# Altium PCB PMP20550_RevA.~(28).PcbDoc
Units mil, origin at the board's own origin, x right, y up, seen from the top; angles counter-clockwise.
Board outline 3847.52 x 1857.32 mil, 2 copper layers (Top Layer, Bottom Layer), stack 62 mil thick; 56 components, 23 nets, 129 pads, 22 vias.
Unrouted connection lines stored in the file: 87.
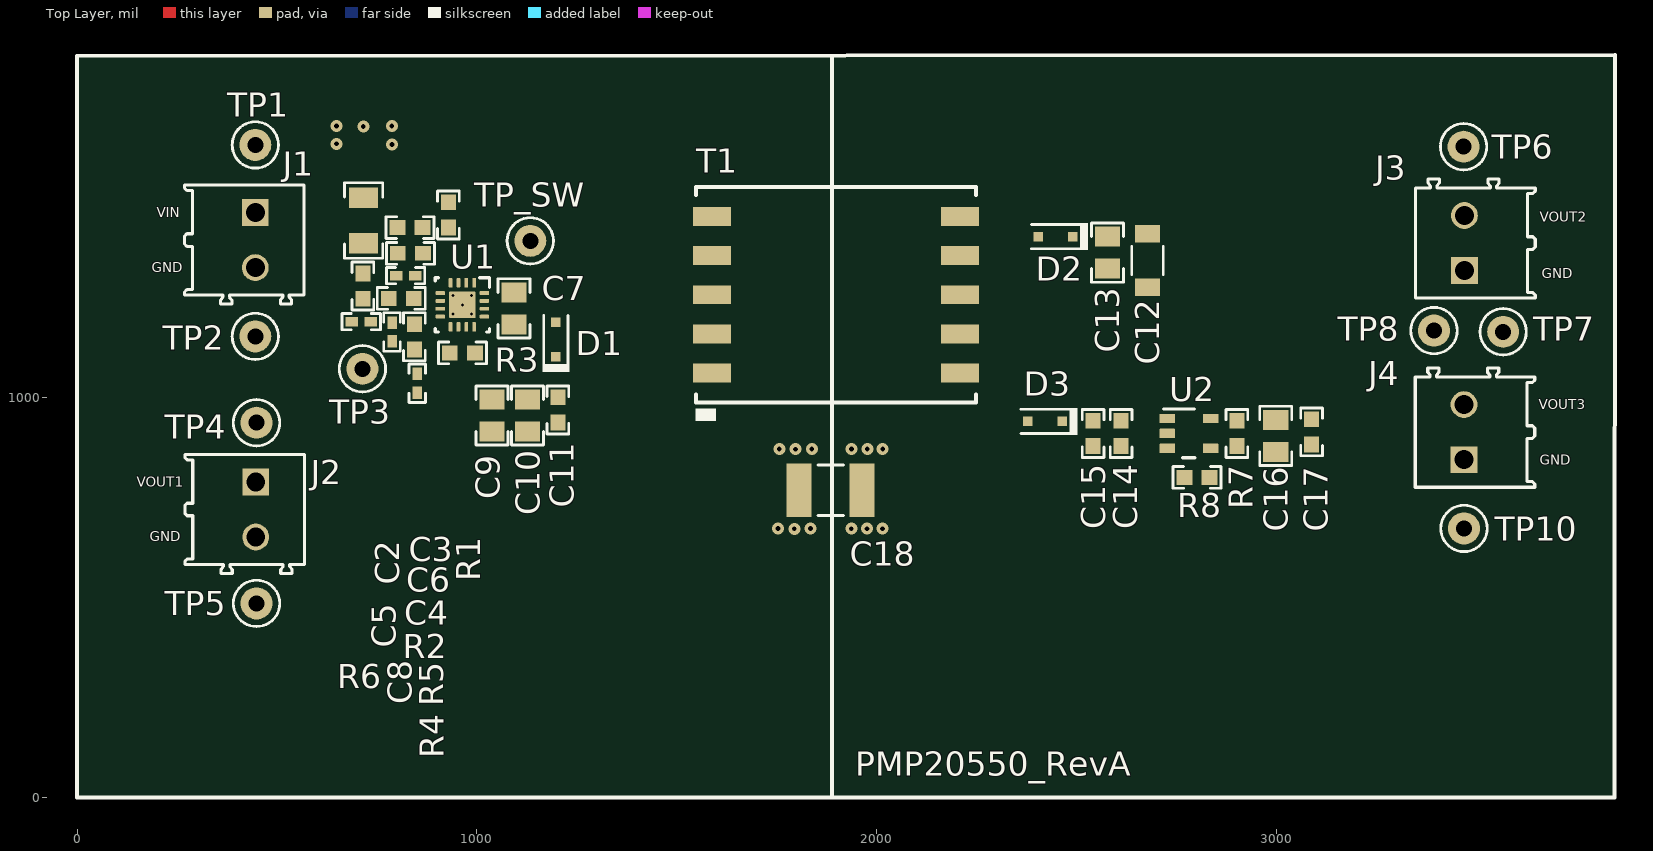
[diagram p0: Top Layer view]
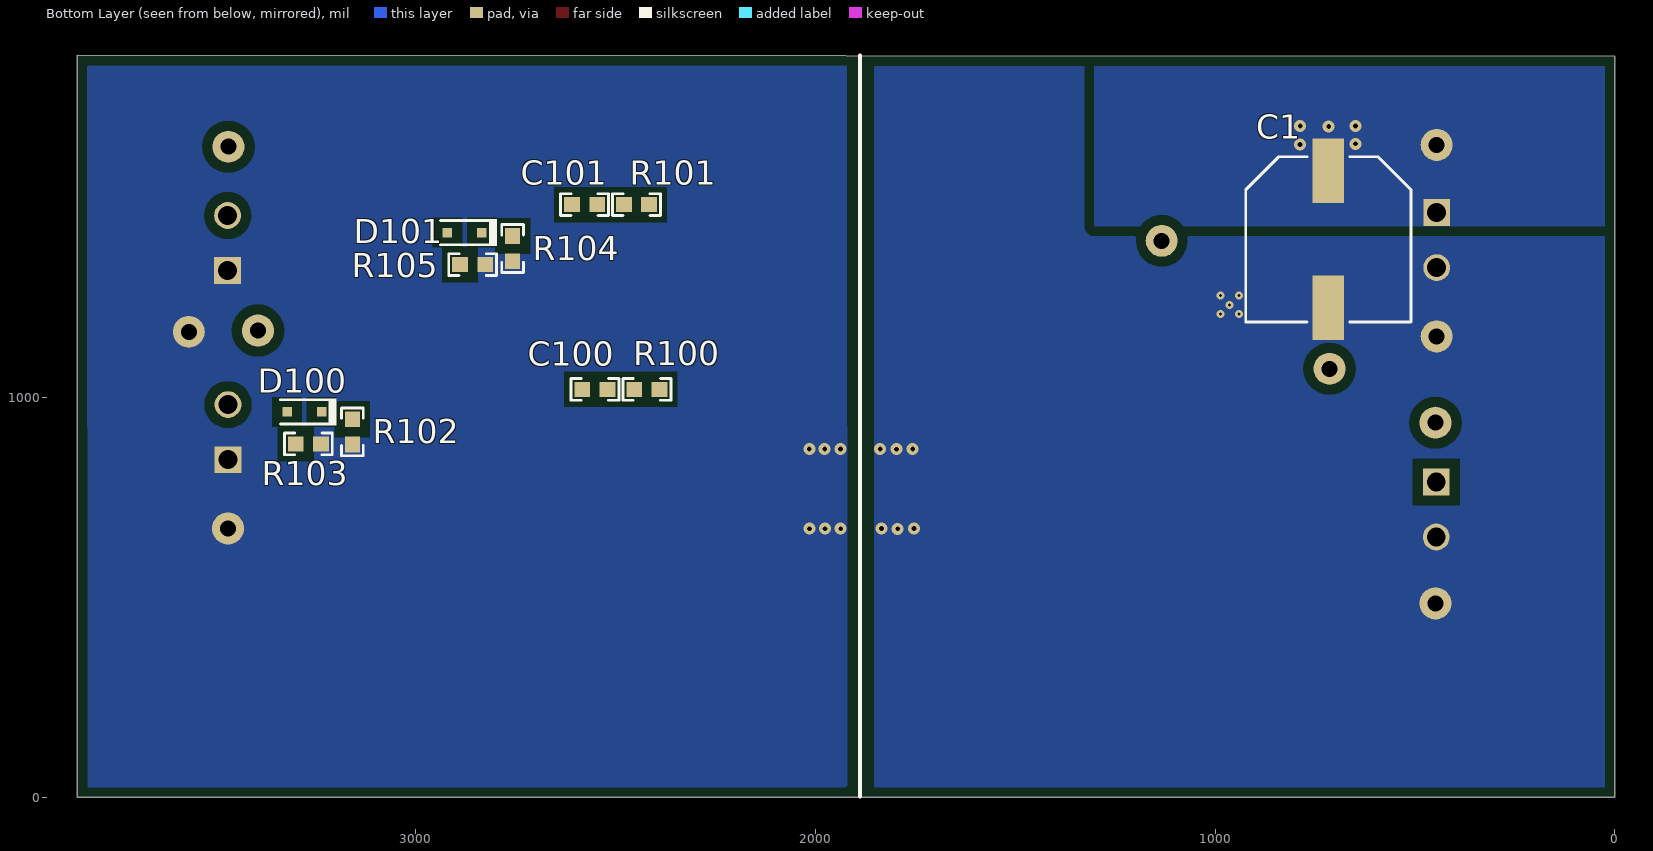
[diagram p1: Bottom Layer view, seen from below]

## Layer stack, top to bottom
Top Solder: solder mask 0.4, Solder Resist, Dk 3.5
Top Layer: signal copper 1.4
Dielectric1: core 59.2, FR-4, Dk 4.8
Bottom Layer: signal copper 1.4
Bottom Solder: solder mask 0.4, Solder Resist, Dk 3.5

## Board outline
0,0 3846.68,-0.46 3847.52,1856.86 0,1854

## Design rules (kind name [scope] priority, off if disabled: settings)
AcuteAngle [All] p1: minimum=4.50000000000000E+0001 checktracksonly=FALSE
AssemblyTestPointUsage [All] p1: valid=2
BoardOutlineClearance BoardOutlineClearance_MountingHoles [OnCopper and InComponentClass('Mounting Holes')] p1: gap=40
BoardOutlineClearance BoardOutlineClearance_Poly [OnCopper and IsPoly] p2: gap=25
BoardOutlineClearance [OnCopper and Not InComponentClass('Logo') and not InComponentClass('FiducialMark') and not InRegion(1000,500,4000,800) and not InPoly] p3: gap=75
Clearance Clearance_Keepouts [((IsTrack Or IsArc) And Not InPoly) And IsFree and IsKeepOut vs ((IsTrack Or IsArc) And Not InPoly) And IsFree and IsKeepOut] p1: gap=0
Clearance Clearance_Poly [InPolygon] p2: gap=25
Clearance [All] p3: gap=7.87
ComponentClearance ComponentClearance_MountingHoles_FiducialMarks [InComponentClass('Mounting Holes') vs InComponentClass('FiducialMark')] p1: gap=50 collisioncheckmode=3 verticalgap=10 showdistances=FALSE
ComponentClearance ComponentClearance_Shunt [InComponentClass('Header') vs InComponentClass('Shunt')] p2: gap=0 collisioncheckmode=3 verticalgap=0 showdistances=FALSE
ComponentClearance ComponentClearance_Logo [InComponentClass('Logo')] p3: gap=50 collisioncheckmode=3 verticalgap=10 showdistances=FALSE
ComponentClearance ComponentClearance_ScrewToNut [(HasFootprint('NY PMS 440 0025 PH')) vs (HasFootprint('Keystone_1902C'))] p4: gap=5 collisioncheckmode=3 verticalgap=10 showdistances=FALSE
ComponentClearance ComponentClearance_MountingHoles [InComponentClass('Mounting Holes')] p5: gap=250 collisioncheckmode=3 verticalgap=100000 showdistances=FALSE
ComponentClearance ComponentClearance_SmallPassives [HasFootprint('0201*') or HasFootprint('0402*') or HasFootprint('0508') or HasFootprint('0603*') or HasFootprint('0612') or HasFootprint('0805*') or HasFootprint('0815*') or HasFootprint('0830*') or HasFootprint('1206*') or HasFootprint('1210*') or HasFootprint('1808*') or HasFootprint('1812*') or HasFootprint('1825*') or HasFootprint('2010*') or HasFootprint('2220*') or HasFootprint('2225*') or HasFootprint('2512*') or HasFootprint('2728*') or HasFootprint('3518*') vs HasFootprint('0201*') or HasFootprint('0402*') or HasFootprint('0508') or HasFootprint('0603*') or HasFootprint('0612') or HasFootprint('0805*') or HasFootprint('0815*') or HasFootprint('0830*') or HasFootprint('1206*') or HasFootprint('1210*') or HasFootprint('1808*') or HasFootprint('1812*') or HasFootprint('1825*') or HasFootprint('2010*') or HasFootprint('2220*') or HasFootprint('2225*') or HasFootprint('2512*') or HasFootprint('2728*') or HasFootprint('3518*')] p6: gap=14.96 collisioncheckmode=3 verticalgap=10 showdistances=FALSE
ComponentClearance ComponentClearance_THtoSMT [IsThruComponent vs IsSMTComponent] p7: gap=40 collisioncheckmode=3 verticalgap=30 showdistances=FALSE
ComponentClearance ComponentClearance_THtoTH [IsThruComponent vs IsThruComponent] p8: gap=30 collisioncheckmode=3 verticalgap=30 showdistances=FALSE
ComponentClearance [All] p9: gap=30 collisioncheckmode=3 verticalgap=10 showdistances=FALSE
DiffPairsRouting [All] p1: maxlimit=100 minlimit=10 mostfreqgap=10 toplayer_minwidth=15 toplayer_maxwidth=15 toplayer_prefwidth=15 bottomlayer_minwidth=15 bottomlayer_maxwidth=15 bottomlayer_prefwidth=15 maxuncoupledlength=1000
FabricationTestPointUsage TestPointUsage [All] p1: valid=2 allowmultiple=FALSE
FabricationTestpoint Testpoint [All] p1: side=3 testpointundercomponent=TRUE minsize=40 maxsize=100 preferedsize=60 minholesize=0 maxholesize=40 preferedholesize=32 testpointgrid=1 allowsidetop=TRUE allowsidebottom=TRUE usegrid=TRUE gridtolerance=0.01
FanoutControl Fanout_LCC [IsLCC] p1: bgadir=Out bgaviamode=Centered fanoutstyle=Auto fanoutdirection=Alternating viagrid=1 // Fanout_LCC (Default Rule)
FanoutControl Fanout_BGA [IsBGA] p2: bgadir=Out bgaviamode=Centered fanoutstyle=Auto fanoutdirection=Alternating viagrid=1 // Fanout_BGA (Default Rule)
FanoutControl Fanout_Default [All] p4: bgadir=Out bgaviamode=Centered fanoutstyle=Auto fanoutdirection=Alternating viagrid=1 // Fanout_Default (Default Rule)
FanoutControl Fanout_Small [(CompPinCount < 5)] p5: bgadir=Out bgaviamode=Centered fanoutstyle=Auto fanoutdirection=OutThenIn viagrid=1 // Fanout_Small (Default Rule)
HoleSize [All] p1: absolutevalues=TRUE maxlimit=251 minlimit=7.87 maxpercent=80.000 minpercent=20.000
MinimumAnnularRing MinimumAnnularRing_ThermalPadVias [IsVia and InAnyComponent] p1: minimumring=5.91
MinimumAnnularRing [All] p2: minimumring=8
MinimumSolderMaskSliver MinimumSolderMaskSliver_Logo [InComponentClass('Logo') vs InComponentClass('Logo')] p1: minsoldermaskwidth=0.7
MinimumSolderMaskSliver [All] p2: minsoldermaskwidth=3.94
PlaneConnect [All] p1: planeconnectstyle=Direct reliefexpansion=10 reliefentries=4 reliefconductorwidth=10 reliefairgap=10
PolygonConnect [All] p1: connectstyle=Direct reliefconductorwidth=10 reliefentries=4 polygonreliefangle="90 Angle" airgapwidth=10
RoutingVias ThermalPadVias [IsVia and InAnyComponent] p1: holewidth=7.87 width=19.68 viastyle="Through Hole" minholewidth=7.87 minwidth=19.68 maxholewidth=12.99 maxwidth=23.62
RoutingVias [All] p2: holewidth=16 width=34 viastyle="Through Hole" minholewidth=7.87 minwidth=26 maxholewidth=40 maxwidth=65
SilkToBoardRegionClearance [Not ((IsComment or IsDesignator) And (Hide <> 'False')) and not InRegion(1000,500,4000,800)] p1:
SilkToSilkClearance SilkToSilkClearance_Pb-FreeLogo [(HasFootprint('Pb-Free_Overlay_Medium') OR HasFootprint('Pb-Free_Overlay_Small')) vs (HasFootprint('Pb-Free_Overlay_Medium') OR HasFootprint('Pb-Free_Overlay_Small'))] p1: silktosilkclearance=0
SilkToSilkClearance [All] p2: silktosilkclearance=4
SilkToSolderMaskClearance SilkToComponentPadClearance [IsPad and InAnycomponent] p1: minsilkscreentomaskgap=5 clearancetoexposedcopper=TRUE
SilkToSolderMaskClearance "Silk to Solder Mask Opening" [All] p2: minsilkscreentomaskgap=4 clearancetoexposedcopper=FALSE
SolderMaskExpansion [All] p1: expansion=1.97
Width [All] p1: maxlimit=100 minlimit=6 preferedwidth=10 checkconnectedcopper=TRUE
15 further rules are at their usual default settings.

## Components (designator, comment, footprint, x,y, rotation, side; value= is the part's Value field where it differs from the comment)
C1 "EEE-FC1V221P" SM_RADIAL_G 717,1395.74 r270 bottom
C2 "GMK316AB7106KL" 1206 717,1443 r270 top
C3 "C1608X7R1E104K080AA" 0603 833,1425 r180 top
C4 "GRM155R71E333KA88D" 0402 822,1305 r180 top
C5 "C1608X7R1E104K080AA" 0603 715,1279 r90 top
C6 "C1608X7R1E104K080AA" 0603 834,1361 r180 top
C7 "LMK212B7105KG-T" 0805_HV 1093,1223 r90 top
C8 "GRM1555C1H201JA01D" 0402 788,1164 r90 top
C9 "GRM21BZ71A226ME15L" 0805_HV 1038,955 r270 top
C10 "GRM21BZ71A226ME15L" 0805_HV 1127,955 r270 top
C11 "C0603X104K8RACTU" 0603 1203,969 r270 top
C12 "C3216X5R1E336M160AC" 1206_180 2677.89,1342.69 r270 top
C13 "08053C104KAT2A" 0805_HV 2577.89,1362.69 r270 top
C14 "GRM188Z71A106MA73D" 0603 2611.89,910.26 r270 top
C15 "C1608X7R1E104K080AA" 0603 2541.89,910.26 r270 top
C16 "C2012X7R1E474K125AA" 0805_HV 2998.89,904.26 r270 top
C17 "C0603X104K8RACTU" 0603 3088.89,914.26 r270 top
C18 "GR443QR73D102KW01L" 1812 1885.21,768 r180 top
C100 "GRM1885C1H111JA01D" 0603 2551.89,1020.26 r180 bottom
C101 "GRM1885C1H111JA01D" 0603 2577.89,1482.69 r180 bottom
D1 "PMEG2020EJ,115" SOD-323F 1198,1145 r90 top
D2 "PMEG2020EJ,115" SOD-323F 2447.89,1402.69 r180 top
D3 "PMEG2020EJ,115" SOD-323F 2421.89,940.26 r180 top
D100 "MMSZ5235BS-7-F" SOD-323 3278.89,964.26 r0 bottom
D101 "MMSZ5235BS-7-F" SOD-323 2877.89,1412.69 r0 bottom
J1 "1984617" Phoenix_1984617 446,1394 r270 top
J2 "1984617" Phoenix_1984617 447,720 r270 top
J3 "1984617" Phoenix_1984617 3470.89,1386.57 r90 top
J4 "1984617" Phoenix_1984617 3469.89,913.57 r90 top
R1 "ERJ-3GEY0R00V" 0603 929,1457 r90 top
R2 "RC0603FR-073K01L" 0603 811,1248 r0 top
R3 "CRCW0603162KFKEA" 0603 964,1112 r180 top
R4 "ERJ-2RKF49R9X" 0402 851,1036 r270 top
R5 "CRCW060330K9FKEA" 0603 844,1152 r270 top
R6 "ERJ-2RKF1002X" 0402 711,1190 r0 top
R7 "RC0603FR-0778K7L" 0603 2901.89,910.26 r90 top
R8 "CRCW060324K9FKEA" 0603 2801.89,800.26 r0 top
R100 "CPF0603B1K62E" 0603 2421.89,1020.26 r180 bottom
R101 "CPF0603B1K62E" 0603 2447.89,1482.69 r180 bottom
R102 "CPF0603B1K62E" 0603 3158.89,914.26 r270 bottom
R103 "CPF0603B1K62E" 0603 3268.89,884.26 r180 bottom
R104 "CPF0603B1K62E" 0603 2757.89,1372.69 r270 bottom
R105 "CPF0603B1K62E" 0603 2857.89,1332.69 r180 bottom
T1 "PA4134NL" Pulse_PA4065NL 1898.44,1257.17 r90 top
TP1 "5000" Keystone5000 446,1632 r90 top
TP2 "5001" Keystone5001 446,1153 r90 top
TP3 "5003" Keystone5003 714,1072 r0 top
TP4 "VBUS" Keystone5000 449,937 r90 top
TP5 "5001" Keystone5001 449,485 r90 top
TP6 "5000" Keystone5000 3468.89,1627.57 r0 top
TP7 "5001" Keystone5001 3567.89,1164.57 r0 top
TP8 "5000" Keystone5000 3394.89,1167.57 r0 top
TP10 "5001" Keystone5001 3469.89,672.57 r90 top
TP_SW "5001" Keystone5001 1134,1392 r90 top
U1 "TPS55340QRTERQ1" RTE0016C 964,1232 r270 top
U2 "TPS73201QDBVRQ1" DBV0005A_N 2781.89,910.26 r0 top

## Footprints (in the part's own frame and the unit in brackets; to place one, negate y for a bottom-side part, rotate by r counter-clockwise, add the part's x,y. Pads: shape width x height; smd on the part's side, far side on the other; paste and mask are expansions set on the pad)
0402 [mm] "0402 from SM-752 data"
  rect 0.8x0.6 smd: 1(-0.6,0) 2(0.6,0)
  silkscreen extent -1.22,-0.52 1.22,0.52, body extent -0.55,-0.3 0.55,0.3, height 0.6
0603 [mm] "0603 from SM-752 data"
  rect 1x0.95 smd: 1(-0.8,0) 2(0.8,0)
  silkscreen extent -1.52,-0.69 1.52,0.69, body extent -0.87,-0.47 0.87,0.47, height 1
0805_HV [mil] "0805 with 30mil clearance between pads"
  rect 50x63 smd: 1(-40,0) 2(40,0)
  silkscreen extent -74,-40 74,40, body extent -43,-29 43,29, height 57
1206 [mm] "1206 from SM-752 data"
  rect 1.3x1.85 smd: 1(-1.45,0) 2(1.45,0)
  silkscreen extent -2.4,-1.21 2.4,1.21, body extent -1.7,-0.9 1.7,0.9, height 1.35
1206_180 [mm] "1206_180"
  rect 1.1x1.6 smd: 1(-1.7,0) 2(1.7,0)
  silkscreen extent -0.9,-1 0.9,1, body extent -1.75,-0.95 1.75,0.95, height 1.8
1812 [mm]
  rect 1.6x3.4 smd: 1(-2,0) 2(2,0)
  silkscreen extent -0.8,-1.6 0.8,1.6, body extent -2.4,-1.7 2.4,1.7, height 1.35
DBV0005A_N [mm] "SOT23, 5-Leads, Body 2.9x1.6mm, Pitch 0.95mm, Lead Span 2.8mm, IPC Medium Density"
  rrect17% 1x0.6 smd: 1(-1.375,0.95) 2(-1.375,0) 3(-1.375,-0.95) 4(1.375,-0.95) 5(1.375,0.95)
  silkscreen extent -1.63,-1.55 0.38,1.55, body extent -1.42,-1.46 1.42,1.46, height 1.09
Keystone5000 [mil] "For Keystone 500x miniature loop terminals"
  round 80 hole 40: 1(0,0)
  silkscreen extent -58,-58 58,58, body extent -49,-49 49,49, height 182
Keystone5001 [mil] "For Keystone 500x miniature loop terminals"
  round 80 hole 40: 1(0,0)
  silkscreen extent -58,-58 58,58, body extent -49,-49 49,49, height 182
Keystone5003 [mil] "For Keystone 500x miniature loop terminals"
  round 80 hole 40: 1(0,0)
  silkscreen extent -58,-58 58,58, body extent -49,-49 49,49, height 182
Phoenix_1984617 [mm] "Terminal Block, 3.5mm, 2x1, TH"
  rect 1.7x1.7 hole 1.2: 1(-1.75,0)
  round 1.7 hole 1.2: 2(1.75,0)
  silkscreen extent -3.5,-4.5 4.07,3.1, body extent -3.5,-4.5 4.07,3.1, height 9
Pulse_PA4065NL [mil] "PULSE"
  rect 47x94.5 smd: 1(-196,310.25) 2(-98,310.25) 3(0,310.25) 4(98,310.25) 5(196,310.25) 6(196,-310.25) 7(98,-310.25) 8(0,-310.25) 9(-98,-310.25) 10(-196,-310.25)
  silkscreen extent -315,-350 270,350, body extent -265,-345 265,343, height 540
RTE0016C [mm] "Texas Insturments"
  rrect42% 0.6x0.24 smd: 1(-1.4,0.75) 2(-1.4,0.25) 3(-1.4,-0.25) 4(-1.4,-0.75) 9(1.4,-0.75) 10(1.4,-0.25) 11(1.4,0.25) 12(1.4,0.75)
  rrect42% 0.24x0.6 smd: 5(-0.75,-1.4) 6(-0.25,-1.4) 7(0.25,-1.4) 8(0.75,-1.4) 13(0.75,1.4) 14(0.25,1.4) 15(-0.25,1.4) 16(-0.75,1.4)
  rrect6% 1.55x1.55 on Top Paste: 17(0,0)
  rrect6% 1.68x1.68 smd paste-0.85: 17(0,0)
  silkscreen extent -1.72,-1.73 1.72,1.73, body extent -1.57,-1.57 1.58,1.58, height 0.81
SM_RADIAL_G [mm] "10 x 10.2mm:  Panasonic G"
  rect 4.1x2 smd: 1(-4.35,0) 2(4.35,0)
  silkscreen extent -5.25,-5.25 5.25,5.25, body extent -5.25,-5.25 5.25,5.25, height 10.5
SOD-323 [mm] "NXP recommended land pattern"
  rect 0.6x0.6 smd paste-0.05: 1(-1.1,0) 2(1.1,0)
  silkscreen extent -2.06,-0.86 1.53,0.86, body extent -1.3,-0.67 1.3,0.68, height 1.1
SOD-323F [mm] "NXP recommended land pattern"
  rect 0.6x0.6 smd paste-0.05: 1(-1.1,0) 2(1.1,0)
  silkscreen extent -2.06,-0.86 1.53,0.86, body extent -1.35,-0.67 1.35,0.68, height 0.79

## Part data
C1: "CAP, AL, 220 µF, 35 V, +/- 20%, 0.15 ohm, SMD"
C2: "CAP, CERM, 10 µF, 35 V, +/- 10%, X7R, 1206"
C3 C5 C6 C15: "CAP, CERM, 0.1 µF, 25 V, +/- 10%, X7R, 0603"
C4: "OPEN, 0402"
C7: "CAP, CERM, 1 µF, 10 V, +/- 10%, X7R, 0805"
C8: "CAP, CERM, 200 pF, 50 V, +/- 5%, C0G/NP0, 0402"
C9 C10: "CAP, CERM, 22 µF, 10 V, +/- 20%, X7R, 0805"
C11 C17: "CAP, CERM, 0.1 µF, 10 V, +/- 10%, X7R, 0603"
C12: "CAP, CERM, 33 µF, 25 V, +/- 20%, X5R, 1206"
C13: "CAP, CERM, 0.1 µF, 25 V, +/- 10%, X7R, 0805"
C14: "CAP, CERM, 10 µF, 10 V, +/- 20%, X7R, 0603"
C16: "CAP, CERM, 4.7 µF, 25 V, +/- 10%, X7R, 0805"
C18: "CAP, CERM, 1000 pF, 2000 V, +/- 10%, X7R, 1812"
C100 C101: "CAP, CERM, 110 pF, 50 V, +/- 5%, C0G/NP0, 0603"
D1 D2 D3: "Diode, Schottky, 20 V, 2 A, SOD-323F"
D100 D101: "Diode, Zener, 6.8 V, 200 mW, SOD-323"
J1 J2 J3 J4: "Terminal Block, 3.5mm, 2x1, TH"
R1: "RES, 0, 5%, 0.1 W, 0603"
R2: "RES, 3.01 k, 1%, 0.1 W, 0603"
R3: "RES, 162 k, 1%, 0.1 W, 0603"
R4: "RES, 49.9, 1%, 0.1 W, AEC-Q200 Grade 0, 0402"
R5: "RES, 30.9 k, 1%, 0.1 W, 0603"
R6: "RES, 10.0 k, 1%, 0.1 W, 0402"
R7: "RES, 78.7 k, 1%, 0.1 W, 0603"
R8: "RES, 24.9 k, 1%, 0.1 W, 0603"
R100 R101 R102 R103 R104 R105: "RES, 1.62 k, 0.1%, 0.063 W, 0603"
T1: "Transformer,  100uH, SMT"
TP1 TP6 TP8: "Test Point, Miniature, Red, TH"
TP2 TP5 TP7 TP10 TP_SW: "Test Point, Miniature, Black, TH"
TP3: "Test Point, Miniature, Orange, TH"
TP4: library part 5000, "Test Point, TH, Miniature, Red"
U1: "Integrated 5-A 40-V Wide Input Range Boost/SEPIC/Flyback DC-DC Regulator, RTE0016C"
U2: "Single Output Fast Transient Response LDO, 250 mA, Adjustable 1.2 to 5.5 V Output, 1.7 to 5.5 V Input, 5-pin SOT-23 (DBV), -40 to 125 degC, Green (RoHS & no Sb/Br)"

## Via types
v1: diameter 30, hole 12, Top Layer to Bottom Layer, 17 vias
v2: diameter 19.68, hole 7.87, Top Layer to Bottom Layer, tented top, 5 vias

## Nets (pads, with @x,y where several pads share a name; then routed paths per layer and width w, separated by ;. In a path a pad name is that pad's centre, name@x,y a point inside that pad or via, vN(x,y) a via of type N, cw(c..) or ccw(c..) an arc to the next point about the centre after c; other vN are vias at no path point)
GND: C1.2 C2.2 C3.2 C4.2 C5.2 C6.2 C9.2 C10.2 C11.2 C18.2 J1.2 J2.2 R3.1 R6.1 T1.1 TP2.1 TP5.1 U1.5 U1.6 U1.11 U1.12 U1.13 U1.17@964,1232
  other v1: 1753.42,672.26 1794.33,671.68 1834.65,672.26 1756.85,871.46 1797.76,870.88 1838.09,871.46
  other v2: 940.77,1208.77 987.23,1208.77 964,1232 940.77,1255.23 987.23,1255.23
GND2: C12.2 C13.2 C14.2 C15.2 C16.2 C17.2 C18.1 J3.1 J4.1 R8.1 R102.2 R103.2 R104.2 R105.2 T1.10 TP7.1 TP10.1 U2.2
  other v1: 1937.07,671.91 1976.25,671.91 2014.85,671.91 1937.86,871.46 1977.03,871.46 2015.63,871.46
NetC1_1: C1.1 C2.1 J1.1 R1.2 T1.5 TP1.1
  other v1: 787.66,1632.86 649.3,1634.93 716.12,1678.1 787.37,1679.28 649.3,1679.57
NetC3_1: C3.1 R1.1 U1.2 U1.3
NetC4_1: C4.1 R2.2 U1.7
NetC5_1: C5.1 R2.1
NetC6_1: C6.1 U1.4
NetC7_1: C7.1 D1.2 T1.2
NetC7_2: C7.2 T1.4 TP_SW.1 U1.1 U1.15 U1.16
NetC8_1: C8.1 R4.1 R5.2 TP3.1
NetC8_2: C8.2 R5.1 R6.2 U1.8
NetC9_1: C9.1 C10.1 C11.1 D1.1 J2.1 R4.2 TP4.1
NetC12_1: C12.1 C13.1 C101.1 D2.1 D101.1 J3.2 R104.1 TP6.1
NetC14_1: C14.1 C15.1 C100.1 D3.1 U2.1 U2.3
NetC16_1: C16.1 C17.1 D100.1 J4.2 R7.2 R102.1 TP8.1 U2.5
NetC100_2: C100.2 R100.1
NetC101_2: C101.2 R101.1
NetD2_2: D2.2 R101.2 T1.6
NetD3_2: D3.2 R100.2 T1.7 T1.9
NetD100_2: D100.2 R103.1
NetD101_2: D101.2 R105.1
NetR3_2: R3.2 U1.9
NetR7_1: R7.1 R8.2 U2.4
pads on no net: T1.3 T1.8 U1.10 U1.14 U1.17@964,1232

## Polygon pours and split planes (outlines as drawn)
GND2 on Bottom Layer "Bottom - GND2" (solid, pour order 4): 1920.43,0 4847,0 4847,1854 1921.43,1854
GND on Bottom Layer "Bottom - GND1" (solid, pour order 2): 0,0 1853.01,0 1853.01,1854 0,1854
NetC1_1 on Bottom Layer "Bottom - VIN" (solid, pour order 0): 0,1854 0.69,1854.69 1302.63,1854.69 1302.63,1428.64 0.8,1428.64

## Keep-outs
Keep-Out Layer:
  text ".Layer_Name" at 577,-858.49 h60

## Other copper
Top Layer:
  text ".Layer_Name" at 577,-858.49 h60
Bottom Layer:
  text ".Layer_Name" at 577,-858.49 h60

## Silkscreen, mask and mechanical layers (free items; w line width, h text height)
Top Overlay:
  lines w10: 1888.57,-0.97 1888.57,1853.08 ; 0,0 3846.68,-0.46 3847.52,1856.86 0,1854 0,0
  text "VIN" at 199,1451 h25
  text "VOUT2" at 3658.89,1439.57 h25
  text "GND" at 187,1314 h25
  text "GND" at 3663.89,1298.57 h25
  text "VOUT3" at 3656.89,970.57 h25
  text "GND" at 3658.89,831.57 h25
  text "VOUT1" at 149,777 h25
  text "GND" at 182,641 h25
  text "PMP20550_RevA" at 1947.14,53.22 h60
  text ".Layer_Name" at 577,-858.49 h60
Bottom Overlay:
  lines w10: 1888.23,1.52 1888.23,1855.26
  text ".Layer_Name" at 577,-858.49 h60
Top Paste:
  text ".Layer_Name" at 577,-858.49 h60
Bottom Paste:
  text ".Layer_Name" at 577,-858.49 h60
Top Solder:
  text ".Layer_Name" at 577,-858.49 h60
  text ".Layer_Name" at 577,-858.49 h60
Bottom Solder:
  text ".Layer_Name" at 577,-858.49 h60
Drill Guide:
  text ".Layer_Name" at 577,-858.49 h60
M1 Board Outline:
  text ".Layer_Name" at 577,-858.49 h60
M2 Board Dimensions:
  rectangle: 125,-400 500,-275
  rectangle: 0,-275 125,-150
  lines w7: 0,-275 1000,-275 ; 125,-400 125,-150 ; 250,-400 250,-150 ; 500,-400 500,-150 ; 750,-400 750,-150 ; 0,-400 0,-150 1000,-150 1000,-400 0,-400
  text ".Layer_Name" at 577,-858.49 h60
M3 3D STEP Top:
  text ".Layer_Name" at 577,-858.49 h60
M4 3D STEP Bottom:
  text ".Layer_Name" at 577,-858.49 h60
M5 Assembly Top:
  lines w10: -292,-930.17 6308,-930.17 ; -292,-726.83 6310,-726.83 ; -292,-523.5 -292,-1133.5 3713,-1133.5 6310,-1133.5 6310,-523.5 -291.5,-523.5 -291.5,-1133.5 1284,-1133.5 ; 2173,-1133.5 2173,-523.5 ; 3440,-726.83 3440,-523.5 ; 4280,-726.83 4280,-523.5 ; 4902,-1140 4902,-937.17
  text "COMPONENTS MARKED 'DNP' SHOULD NOT BE POPULATED." at 1153.5,-318.5 h60
  text "ASSEMBLY VARIANT:" at 1153,-434 h60
  text ".VariantName" at 2189,-434 h60
  text "PCB VIEWED FROM TOP SIDE" at -228.5,-655.67 h60
  text "BOARD #:" at 2248,-655.67 h60
  text ".PRJ_Number" at 2793.5,-655.67 h60
  text "REV:" at 3638,-655.67 h60
  text ".PCB_Rev" at 3929.5,-655.67 h60
  text "SVN REV:" at 4476,-655.67 h60
  text ".VersionControl_RevNumber" at 4982,-655.67 h60
  text "TID #:" at 2248,-859 h60
  text ".TID" at 2793.5,-859 h60
  text "PLOT NAME =" at -228.5,-1064.34 h60
  text ".plot_File_Name" at 577,-1064.34 h60
  text "GENERATED    :" at 2250,-1064.34 h60
  text ".Print_Date" at 3119.5,-1064.34 h60
  text ".Print_Time" at 3848.5,-1064.34 h60
  text "TEXAS INSTRUMENTS" at 5113,-1064.34 h60
M6 Assembly Bottom:
  lines w10: -292.5,-727.33 6309.5,-727.33 ; -290.5,-930.67 6309.5,-930.67 ; 1115.5,-1140.5 1115.5,-937.67 ; 1737.5,-727.33 1737.5,-524 ; 2577.5,-727.33 2577.5,-524 ; 3844.5,-1134 3844.5,-524 ; 4733.5,-1134 6309,-1134 6309,-524 -292.5,-524 -292.5,-1134 2304.5,-1134 6309.5,-1134 6309.5,-524
  text "COMPONENTS MARKED 'DNP' SHOULD NOT BE POPULATED." at 6102,-318 h60
  text ".VariantName" at 5058,-434 h60
  text "ASSEMBLY VARIANT:" at 6097,-434 h60
  text ".VersionControl_RevNumber" at 1035.5,-656.17 h60
  text "SVN REV:" at 1541.5,-656.17 h60
  text ".PCB_Rev" at 2088,-656.17 h60
  text "REV:" at 2379.5,-656.17 h60
  text ".PRJ_Number" at 3224,-656.17 h60
  text "BOARD #:" at 3769.5,-656.17 h60
  text "PCB VIEWED FROM BOTTOM SIDE" at 6246,-656.17 h60
  text ".TID" at 3224,-859.5 h60
  text "TID #:" at 3769.5,-859.5 h60
  text "TEXAS INSTRUMENTS" at 904.5,-1064.84 h60
  text ".Print_Time" at 2169,-1064.84 h60
  text ".Print_Date" at 2898,-1064.84 h60
  text "GENERATED    :" at 3767.5,-1064.84 h60
  text ".plot_File_Name" at 5440.5,-1064.84 h60
  text "PLOT NAME =" at 6246,-1064.84 h60
M9 Title Sheet:
  drawing of 57 lines, arcs and shapes, not listed
  text "1" at 739.84,8036.5 h70
  text "2" at 3235.5,8036.5 h70
  text "3" at 5724.84,8036.5 h70
  text "4" at 8231.51,8036.5 h70
  text "5" at 10730.5,8036.5 h70
  text "6" at 13235.5,8036.5 h70
  text "A" at -416.5,6893.5 h70
  text "A" at 14383.5,6893.5 h70
  text "B" at -416.5,4513.5 h70
  text "B" at 14383.5,4513.5 h70
  text "C" at -416.5,2138.5 h70
  text "C" at 14383.5,2138.5 h70
  text "PROJECT TITLE:" at 11343.5,277.5 h45
  text ".PRJ_Title" at 11393.5,144.17 h70
  text "DESIGNED FOR:" at 11343.5,-23.5 h45
  text ".PRJ_Customer" at 11393.5,-163.5 h70
  text "D" at -416.5,-231.5 h70
  text "D" at 14383.5,-231.5 h70
  text "FILE NAME:" at 11343.5,-323.5 h45
  text ".PCB_File_Name_No_Path" at 11393.5,-443.5 h70
  text "Texas Instruments (TI) and/or its licensors do not warrant the accuracy or completeness of this specification" at 6374,-605.34 h45
  text "ENGINEER:" at 11343.5,-613.5 h45
  text "LAYOUT BY:" at 12848.5,-613.5 h45
  text "or any information contained therein. TI and/or its licensors do not warrant that this design will meet" at 6329.01,-718 h45
  text ".PRJ_Engineer" at 11393.5,-768.49 h70
  text ".PCB_Layout" at 12899,-768.49 h70
  text "the specifications, will be suitable for your application or fit for any particular purpose, or will operate in" at 6329.01,-830.67 h45
  text ".Layer_Name" at 577,-858.49 h60
  text "ALTIUM DESIGNER VERSION:" at 12848.5,-923.5 h45
  text "an implementation. TI and/or its licensors do not warrant that the design is production worthy. You should" at 6329.01,-943.33 h45
  text "completely validate and test your design implementation to confirm the system functionality for your application." at 6374,-1056 h45
  text ".print_Scale" at 11393.5,-1056.83 h70
  text ".Application_BuildNumber" at 12899,-1056.83 h70
  text "1" at 739.84,-1263.5 h70
  text "2" at 3235.5,-1263.5 h70
  text "3" at 5724.84,-1263.5 h70
  text "4" at 8231.51,-1263.5 h70
  text "5" at 10730.5,-1263.5 h70
  text "6" at 13235.5,-1263.5 h70
M10 Fab Notes:
  drawing of 173 lines, arcs and shapes, not listed
  text "DESIGN INFORMATION" at 12378.02,6201 h60
  text "MIN. TRACK WIDTH:" at 11733.46,6021 h60
  text "8" at 12829.7,6021 h60
  text "MIL" at 12984.46,6021 h60
  text "MIN. CLEARANCE:" at 11733.46,5889 h60
  text "0.2" at 12769.7,5889 h60
  text "mm" at 12984.46,5889 h60
  text "MIN. VIA PAD SIZE:" at 11733.46,5757 h60
  text "24" at 12799.71,5757 h60
  text "MIL" at 12984.46,5757 h60
  text "0.05mm (2MIL)" at 12428.46,5615.29 h60
  text "MINIMUM ANNULAR RING" at 11404.23,5611 h60
  text "EXTERNAL" at 13136.46,5611 h60
  text "PER" at 11604.23,5493 h60
  text "IPC-D-275 CLASS 2 LEVEL C" at 11824.23,5493 h60
  text "MIL, HOLES" at 13312.46,5380.71 h60
  text "+/-" at 12920,5380 h60
  text "+/-" at 13774,5380 h60
  text "REGISTRATION TOLERANCES:" at 11404.23,5375 h60
  text "METAL" at 12604,5375 h60
  text "5" at 13180.2,5375 h60
  text "3" at 14013.2,5375 h60
  text "MIL" at 14129.46,5375 h60
  text "+/-" at 13774,5262 h60
  text "HOLE SIZE TOLERANCE (UNLESS OTHERWISE SPECIFIED):" at 11404.23,5257 h60
  text "3" at 14013.2,5257 h60
  text "MIL" at 14129.46,5257 h60
  text "MATERIAL:" at 11329.46,5047.54 h60
  text "FR-4 High Tg" at 12315.9,4907.21 h60
  text "FR-408" at 11750.46,4898.64 h60
  text "OTHER" at 13238.46,4898.64 h60
  text "X" at 12161,4895 h60
  text "62 MIL (1.6mm) +/-10%" at 12070.56,4735.92 h60
  text "THICKNESS:" at 11404.23,4731.64 h60
  text "X" at 11942.4,4731.64 h60
  text "OTHER" at 13355.46,4731.64 h60
  text "TOLERANCE:" at 11404.23,4573.64 h60
  text "X" at 12243.53,4573.64 h60
  text "ANSI IPC-6012 TYPE 3 CLASS 2" at 12430.48,4573.64 h60
  text "OTHER +/-" at 12430.46,4417.64 h60
  text "BOW & TWIST:" at 11404.23,4260.64 h60
  text "X" at 12243.53,4260.64 h60
  text "ANSI IPC-6012 TYPE 3 CLASS 2" at 12430.48,4260.64 h60
  text "OTHER +/-" at 12430.46,4102.13 h60
  text "DRILLING:" at 11329.46,3963.64 h60
  text "REFERENCE:" at 11404.23,3846.64 h60
  text "X" at 12052.46,3846.64 h60
  text "AS SHOWN" at 12239.46,3846.64 h60
  text "X" at 12953.46,3846.64 h60
  text "NC_DRILL FILES" at 13090.46,3846.64 h60
  text "PTH COPPER THICKNESS:" at 11404.23,3688.64 h60
  text "X" at 12534.46,3688.64 h60
  text "20-30 um" at 12671.46,3688.64 h60
  text "OTHER" at 13388.46,3688.64 h60
  text "BOARD FINISH:" at 11329.46,3529.64 h60
  text "SILKSCREEN:" at 11484.68,3411.64 h60
  text "X" at 12433.46,3411.64 h60
  text "TOP" at 12559.46,3411.64 h60
  text "X" at 12943.46,3411.64 h60
  text "BOTTOM" at 13070.46,3411.64 h60
  text "SILKSCREEN COLOR:" at 11484.68,3244.64 h60
  text "X" at 12432.42,3244.64 h60
  text "WHITE" at 12559.46,3244.64 h60
  text "OTHER" at 13070.46,3244.64 h60
  text "X" at 12563.42,3085.44 h60
  text "GREEN" at 12690.46,3085.44 h60
  text "OTHER" at 13308.46,3085.44 h60
  text "SOLDER RESIST COLOR:" at 11484.68,3074.64 h60
  text "X" at 12563.42,2915.44 h60
  text "MATTE" at 12690.46,2915.44 h60
  text "SEMI-GLOSS" at 13308,2914.8 h60
  text "IMMERSION GOLD (ENIG)" at 12390.46,2726.92 h60
  text "ENEPIG" at 13728,2723.64 h60
  text "SURFACE FINISH:" at 11329.46,2722.64 h60
  text "X" at 12203.51,2722.64 h60
  text "IMM. TIN/SILVER OR EQUIV" at 11659,2565.64 h60
  text "OTHER" at 13090.46,2565.64 h60
  text "ARRAY/PANEL:" at 11329.46,2386.64 h60
  text "CUT AND TRIM PER M1 BOARD OUTLINE" at 12390.46,2382.35 h60
  text "N.C. ROUTE" at 12390.46,2230.64 h60
  text "X" at 13069.46,2230.64 h60
  text "V. SCORE" at 13256.46,2230.64 h60
  text "CERTIFICATION:" at 11329.46,2093.64 h60
  text "MATERIALS AND WORKMANSHIP FOR ALL PCBS" at 12054.46,2093.64 h60
  text "TO MEET OR EXCEED THE REQUIREMENTS OF:" at 12054.46,1995.64 h60
  text "X" at 11680.96,1859.13 h60
  text "ANSI IPC-A-600F CLASS ->" at 11819.96,1859.13 h60
  text "X" at 13459.02,1859.13 h60
  text "2" at 13577.96,1859.14 h60
  text "1" at 13262.96,1857.64 h60
  text "3" at 13931.96,1857.64 h60
  text "X" at 12495.02,1699.64 h60
  text "RoHS" at 12631.96,1699.64 h60
  text "OTHER" at 13276.36,1699.64 h60
  text "PER ORDER" at 13673.42,1699.64 h60
  text "ALL BOARDS MUST MEET OR EXCEED UL94-V0 REQUIREMENTS." at 11357,1534 h60
  text "PCB MUST BEAR THE UL94V-0 UL REGISTERED MATERIAL ID NUMBER" at 11357,1414 h60
  text "ADDITIONAL REQUIREMENTS:" at 11329.46,1240.64 h60
  text "MICROSECTION:" at 11404.23,1125.64 h60
  text "YES" at 12309.96,1125.64 h60
  text "REQUIRED" at 13171.46,969.49 h60
  text "BARE BOARD ELEC. TEST:" at 11404.23,966.64 h60
  text "NONE" at 12709.96,966.64 h60
  text "X" at 13044.46,966.64 h60
  text "PER ORDER" at 13763.46,966.64 h60
  text ".Layer_Name" at 577,-858.49 h60
M11 Gerber Information:
  lines w10: -292,-930.17 6308,-930.17 ; -292,-726.83 6310,-726.83 ; -292,-523.5 -292,-1133.5 3713,-1133.5 6310,-1133.5 6310,-523.5 -291.5,-523.5 -291.5,-1133.5 1284,-1133.5 ; 2173,-1133.5 2173,-523.5 ; 3440,-726.83 3440,-523.5 ; 4280,-726.83 4280,-523.5 ; 4902,-1140 4902,-937.17
  text "ALL ARTWORK VIEWED FROM TOP SIDE" at -228.5,-655.67 h60
  text "BOARD #:" at 2248,-655.67 h60
  text ".PRJ_Number" at 2793.5,-655.67 h60
  text "REV:" at 3638,-655.67 h60
  text ".PCB_Rev" at 3929.5,-655.67 h60
  text "SVN REV:" at 4476,-655.67 h60
  text ".VersionControl_RevNumber" at 4982,-655.67 h60
  text "LAYER NAME =" at -228.5,-858.49 h60
  text "TID #:" at 2248,-859 h60
  text ".TID" at 2793.5,-859 h60
  text "PLOT NAME =" at -228.5,-1064.34 h60
  text ".plot_File_Name" at 577,-1064.34 h60
  text "GENERATED    :" at 2250,-1064.34 h60
  text ".Print_Date" at 3119.5,-1064.34 h60
  text ".Print_Time" at 3848.5,-1064.34 h60
  text "TEXAS INSTRUMENTS" at 5113,-1064.34 h60
M12 Stackup:
  text ".Layer_Name" at 577,-858.49 h60
M13 Component Bodies Top:
  text ".Layer_Name" at 577,-858.49 h60
M14 Component Bodies Bottom:
  text ".Layer_Name" at 577,-858.49 h60
M15 Courtyards Top:
  text ".Layer_Name" at 577,-858.49 h60
M16 Courtyards Bottom:
  text ".Layer_Name" at 577,-858.49 h60
Drill Drawing:
  text ".Layer_Name" at 577,-858.49 h60
M17 Embedded Cavity:
  text ".Layer_Name" at 577,-858.49 h60
M18 Embedded Assembly:
  text ".Layer_Name" at 577,-858.49 h60
M19 Embedded Keepout:
  text ".Layer_Name" at 577,-858.49 h60

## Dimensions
0,-400 to 1000,-400 on M2 Board Dimensions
